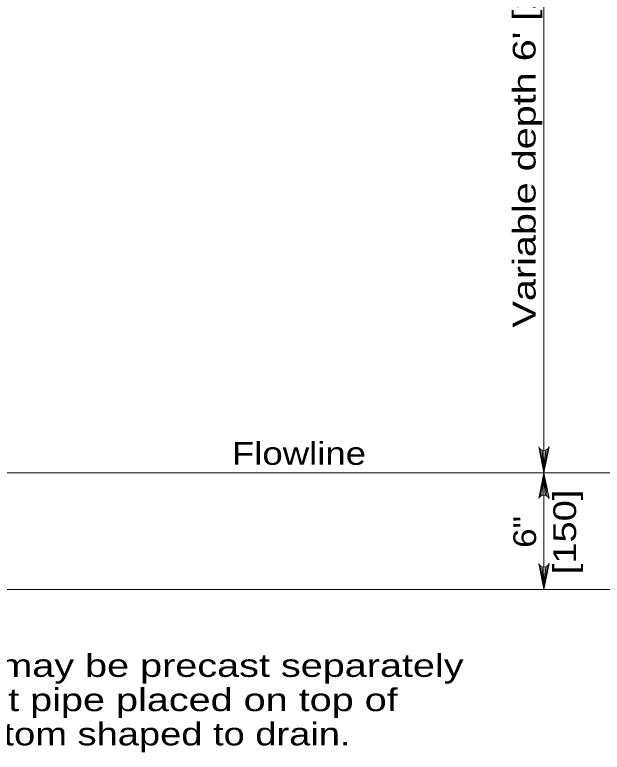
# Model space of a CAD drawing. Extents: x -410.5 to -376.5, y 1617.6 to 1661.6.
# Drawn here: x -400.12 to -396.1, y 1651.02 to 1656.07 of the extents above; entities that cross this region are included whole.
import ezdxf
from ezdxf.enums import TextEntityAlignment as Align

# ---------------------------------------------------------------- set-up
doc = ezdxf.new("R2010")
doc.units = 0
doc.header["$LTSCALE"] = 0.062
doc.layers.add('1', color=7, linetype='Continuous', lineweight=13)

msp = doc.modelspace()

# ---------------------------------------------------------------- linework, layer by layer
at = {"layer": '1'}
for p, q in [((-396.50017, 1658.02708), (-396.50017, 1655.1135)), ((-396.50017, 1655.1135), (-396.50017, 1652.9315)), ((-396.52258, 1653.09175), (-396.50017, 1652.9315)), ((-396.47542, 1653.09358), (-396.50017, 1652.9315)), ((-396.5115, 1653.08625), (-396.50017, 1652.9315)), ((-396.48583, 1653.0875), (-396.50017, 1652.9315)), ((-396.50017, 1653.08467), (-396.50017, 1652.9315)), ((-395.31625, 1652.9315), (-400.54525, 1652.9315)), ((-396.525, 1652.76933), (-396.50017, 1652.9315)), ((-396.51458, 1652.7755), (-396.50017, 1652.9315)), ((-396.50017, 1652.77833), (-396.50017, 1652.9315)), ((-396.48892, 1652.77667), (-396.50017, 1652.9315)), ((-396.47775, 1652.77125), (-396.50017, 1652.9315)), ((-396.52258, 1652.29217), (-396.50017, 1652.13192)), ((-396.5115, 1652.28675), (-396.50017, 1652.13192)), ((-396.47542, 1652.29408), (-396.50017, 1652.13192)), ((-396.48583, 1652.28792), (-396.50017, 1652.13192)), ((-396.50017, 1652.28508), (-396.50017, 1652.13192)), ((-400.54525, 1652.13192), (-395.02575, 1652.13192))]:
    msp.add_line(p, q, dxfattribs=at)
for points in [[(-396.46483, 1653.1085), (-396.50017, 1652.9315), (-396.53558, 1653.1085)], [(-396.53558, 1652.7545), (-396.50017, 1652.9315), (-396.46483, 1652.7545)], [(-396.50017, 1652.9315), (-396.50017, 1652.4), (-396.50017, 1652.13192)], [(-396.46483, 1652.30892), (-396.50017, 1652.13192), (-396.53558, 1652.30892)]]:
    msp.add_lwpolyline(points, dxfattribs=at)
for centre, start, end in [((-396.50024, 1653.12276), 202.08782, 337.91395), ((-396.50017, 1652.74018), 22.08782, 157.91395), ((-396.50024, 1652.32322), 202.08782, 337.91395)]:
    msp.add_arc(centre, 0.0382, start, end, dxfattribs=at)

# ---------------------------------------------------------------- texts
for s, width, p in [("Variable depth 6' [2 m] max.", 1.3, (-396.55708, 1655.61029)), ('[150]', 1.25, (-396.27958, 1652.52583)), ('6"', 1.15, (-396.55358, 1652.52583))]:
    msp.add_text(s, height=0.156, rotation=90, dxfattribs=dict(at, width=width)).set_placement(p, align=Align.CENTER)
for s, width, p in [('Flowline', 1.2, (-398.63692, 1652.98567)), ('Bottom slab may be precast separately', 1.3, (-401.73825, 1651.53283)), ('and the outlet pipe placed on top of', 1.3, (-401.73825, 1651.29817)), ('it with the bottom shaped to drain.', 1.25, (-401.73825, 1651.0635))]:
    msp.add_text(s, height=0.156, dxfattribs=dict(at, width=width)).set_placement(p)

doc.saveas('drawing.dxf')
